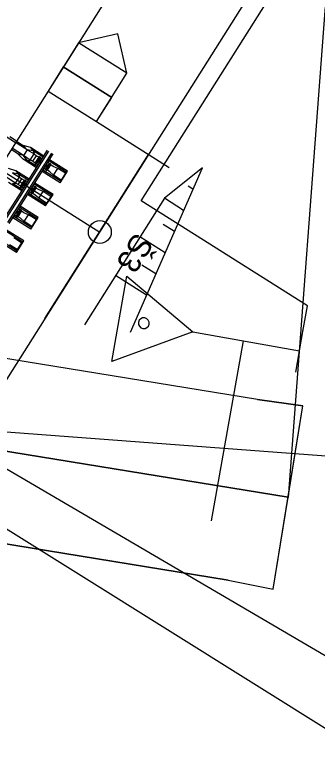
# Model space of a CAD drawing. Extents: x -743359 to -742769, y -1127804 to -1126284.
# Drawn here: x -743170.26 to -743163.64, y -1127104.78 to -1127088.87 of the extents above; entities that cross this region are included whole.
import ezdxf

# ---------------------------------------------------------------- set-up
doc = ezdxf.new("R2010")
doc.units = 0
for name, color, linetype in [('_Zabezpečovací zařízení', 7, 'Continuous'), ('_Zabezpečovací zařízení_trasa', 7, 'Continuous'), ('bublina_fialová_čára_tenká', 7, 'Continuous'), ('KOL_ROST', 7, 'Continuous'), ('KOMUNIKACE_KRAJNICE', 7, 'Continuous'), ('OSA', 7, 'Continuous'), ('OSA_KOMUNIKACE', 7, 'Continuous'), ('SMER_VYS_VYROVNANI', 7, 'Continuous'), ('SRAFA_UPRAVA', 7, 'Continuous'), ('SVAH', 7, 'Continuous'), ('TRATIVOD', 7, 'Continuous')]:
    doc.layers.add(name, color=color, linetype=linetype)

msp = doc.modelspace()

# ---------------------------------------------------------------- linework, layer by layer
at = {"layer": '_Zabezpečovací zařízení'}
for p, q in [((-743168.004, -1127089.286), (-743168.865, -1127089.483)), ((-743167.807, -1127090.147), (-743168.004, -1127089.286)), ((-743168.865, -1127089.483), (-743169.53, -1127090.542)), ((-743167.807, -1127090.147), (-743168.865, -1127089.483)), ((-743169.198, -1127090.012), (-743168.139, -1127090.677)), ((-743168.471, -1127091.206), (-743167.807, -1127090.147)), ((-743169.53, -1127090.542), (-743168.471, -1127091.206)), ((-743168.139, -1127096.449), (-743167.81, -1127094.588)), ((-743167.81, -1127094.588), (-743166.363, -1127095.804)), ((-743166.363, -1127095.804), (-743168.139, -1127096.449)), ((-743166.363, -1127095.804), (-743164.036, -1127096.216)), ((-743164.119, -1127096.681), (-743163.954, -1127095.75)), ((-743165.267, -1127095.997), (-743165.964, -1127099.936))]:
    msp.add_line(p, q, dxfattribs=at)
msp.add_lwpolyline([(-743168.471, -1127091.206), (-743168.139, -1127090.677), (-743169.198, -1127090.012), (-743169.53, -1127090.542), (-743168.471, -1127091.206)], dxfattribs=at)
for start, end in [(79.9608, 259.9608), (259.9608, 79.9608)]:
    msp.add_arc((-743167.437, -1127095.614), 0.118, start, end, dxfattribs=at)
at = {"layer": '_Zabezpečovací zařízení_trasa'}
for points in [[(-743164.036, -1127096.193), (-743163.862, -1127095.231), (-743167.492, -1127092.937), (-743158.53, -1127078.745)], [(-743168.471, -1127091.206), (-743166.88, -1127092.211)]]:
    msp.add_lwpolyline(points, dxfattribs=at)
at = {"layer": 'bublina_fialová_čára_tenká'}
for p, q in [((-743160.679, -1127051.634), (-743164.286, -1127099.423)), ((-743129.509, -1127122.8), (-743175.485, -1127095.847)), ((-743148.502, -1127099.644), (-743174.29, -1127097.707)), ((-743109.419, -1127138.306), (-743174.121, -1127097.814))]:
    msp.add_line(p, q, dxfattribs=at)
at = {"layer": 'KOL_ROST'}
for p, q in [((-743170.487, -1127091.505), (-743170.238, -1127091.662)), ((-743170.219, -1127091.633), (-743170.367, -1127091.539)), ((-743169.988, -1127091.82), (-743170.238, -1127091.662)), ((-743170.219, -1127091.633), (-743170.071, -1127091.726)), ((-743170.188, -1127091.912), (-743170.336, -1127091.819)), ((-743169.916, -1127091.776), (-743170.071, -1127091.726)), ((-743169.988, -1127091.82), (-743170.071, -1127091.726)), ((-743169.988, -1127091.82), (-743170.068, -1127091.947)), ((-743169.988, -1127091.82), (-743169.833, -1127091.912)), ((-743169.857, -1127091.847), (-743169.988, -1127091.82)), ((-743169.916, -1127091.776), (-743169.857, -1127091.847)), ((-743169.624, -1127091.961), (-743169.916, -1127091.776)), ((-743169.864, -1127092.342), (-743169.544, -1127091.834)), ((-743170.077, -1127092.03), (-743170.188, -1127091.912)), ((-743170.068, -1127091.947), (-743170.188, -1127091.912)), ((-743169.988, -1127092.054), (-743170.068, -1127091.947)), ((-743169.918, -1127092.047), (-743169.833, -1127091.912)), ((-743169.861, -1127092.072), (-743169.786, -1127091.953)), ((-743169.857, -1127091.847), (-743169.833, -1127091.912)), ((-743169.639, -1127091.986), (-743169.857, -1127091.847)), ((-743169.833, -1127091.912), (-743169.786, -1127091.953)), ((-743169.831, -1127092.362), (-743169.511, -1127091.855)), ((-743169.786, -1127091.953), (-743169.734, -1127091.98)), ((-743169.77, -1127092.401), (-743169.45, -1127091.894)), ((-743169.737, -1127092.422), (-743169.417, -1127091.914)), ((-743169.734, -1127091.98), (-743169.719, -1127091.976)), ((-743169.661, -1127092.02), (-743169.696, -1127091.997)), ((-743170.077, -1127092.03), (-743169.988, -1127092.054)), ((-743169.784, -1127092.215), (-743170.077, -1127092.03)), ((-743169.988, -1127092.054), (-743169.918, -1127092.047)), ((-743169.768, -1127092.19), (-743169.988, -1127092.054)), ((-743169.861, -1127092.072), (-743169.814, -1127092.107)), ((-743169.814, -1127092.107), (-743169.811, -1127092.123)), ((-743169.747, -1127092.156), (-743169.783, -1127092.134)), ((-743169.754, -1127092.089), (-743169.755, -1127092.081)), ((-743169.716, -1127092.106), (-743169.755, -1127092.081)), ((-743169.716, -1127092.106), (-743169.754, -1127092.089)), ((-743169.725, -1127092.043), (-743169.731, -1127092.043)), ((-743169.731, -1127092.043), (-743169.692, -1127092.068)), ((-743169.692, -1127092.068), (-743169.725, -1127092.043)), ((-743169.692, -1127092.068), (-743169.716, -1127092.106)), ((-743169.565, -1127092.149), (-743169.589, -1127092.186)), ((-743169.525, -1127092.173), (-743169.565, -1127092.149)), ((-743169.565, -1127092.149), (-743169.527, -1127092.167)), ((-743169.5, -1127092.124), (-743169.535, -1127092.101)), ((-743169.12, -1127092.318), (-743169.513, -1127092.067)), ((-743169.102, -1127092.29), (-743169.497, -1127092.041)), ((-743169.47, -1127092.152), (-743169.472, -1127092.135)), ((-743169.47, -1127092.152), (-743169.472, -1127092.135)), ((-743169.419, -1127092.185), (-743169.47, -1127092.153)), ((-743169.419, -1127092.185), (-743169.47, -1127092.153)), ((-743170.237, -1127092.284), (-743170.391, -1127092.234)), ((-743170.237, -1127092.284), (-743170.177, -1127092.354)), ((-743169.944, -1127092.468), (-743170.237, -1127092.284)), ((-743169.262, -1127092.544), (-743169.657, -1127092.295)), ((-743169.245, -1127092.516), (-743169.641, -1127092.269)), ((-743169.584, -1127092.257), (-743169.619, -1127092.235)), ((-743169.589, -1127092.186), (-743169.549, -1127092.211)), ((-743169.589, -1127092.186), (-743169.556, -1127092.213)), ((-743169.545, -1127092.271), (-743169.562, -1127092.277)), ((-743169.556, -1127092.213), (-743169.549, -1127092.211)), ((-743169.494, -1127092.304), (-743169.545, -1127092.271)), ((-743169.527, -1127092.167), (-743169.525, -1127092.173)), ((-743169.412, -1127092.376), (-743169.494, -1127092.304)), ((-743169.318, -1127092.228), (-743169.419, -1127092.185)), ((-743169.318, -1127092.228), (-743169.419, -1127092.185)), ((-743169.412, -1127092.376), (-743169.318, -1127092.228)), ((-743169.149, -1127092.335), (-743169.318, -1127092.228)), ((-743169.262, -1127092.544), (-743169.102, -1127092.29)), ((-743169.117, -1127092.314), (-743169.149, -1127092.335)), ((-743170.308, -1127092.327), (-743170.153, -1127092.419)), ((-743170.177, -1127092.354), (-743170.308, -1127092.327)), ((-743170.239, -1127092.555), (-743170.153, -1127092.419)), ((-743170.184, -1127092.849), (-743169.864, -1127092.342)), ((-743170.181, -1127092.579), (-743170.106, -1127092.461)), ((-743170.177, -1127092.354), (-743170.153, -1127092.419)), ((-743169.96, -1127092.493), (-743170.177, -1127092.354)), ((-743170.153, -1127092.419), (-743170.106, -1127092.461)), ((-743170.151, -1127092.87), (-743169.831, -1127092.362)), ((-743170.106, -1127092.461), (-743170.055, -1127092.488)), ((-743170.09, -1127092.908), (-743169.77, -1127092.401)), ((-743170.057, -1127092.929), (-743169.737, -1127092.422)), ((-743169.242, -1127092.483), (-743169.412, -1127092.376)), ((-743169.149, -1127092.335), (-743169.242, -1127092.483)), ((-743170.104, -1127092.722), (-743170.397, -1127092.537)), ((-743170.308, -1127092.561), (-743170.239, -1127092.555)), ((-743170.089, -1127092.697), (-743170.308, -1127092.561)), ((-743170.181, -1127092.579), (-743170.134, -1127092.614)), ((-743170.134, -1127092.614), (-743170.131, -1127092.63)), ((-743170.074, -1127092.596), (-743170.075, -1127092.589)), ((-743170.036, -1127092.614), (-743170.075, -1127092.589)), ((-743170.036, -1127092.614), (-743170.074, -1127092.596)), ((-743170.055, -1127092.488), (-743170.039, -1127092.484)), ((-743170.045, -1127092.55), (-743170.051, -1127092.551)), ((-743170.051, -1127092.551), (-743170.012, -1127092.576)), ((-743170.012, -1127092.576), (-743170.045, -1127092.55)), ((-743170.012, -1127092.576), (-743170.036, -1127092.614)), ((-743169.981, -1127092.527), (-743170.016, -1127092.504)), ((-743169.82, -1127092.631), (-743169.855, -1127092.608)), ((-743169.44, -1127092.825), (-743169.833, -1127092.574)), ((-743169.422, -1127092.798), (-743169.817, -1127092.549)), ((-743169.247, -1127092.52), (-743169.242, -1127092.483)), ((-743170.067, -1127092.664), (-743170.103, -1127092.642)), ((-743169.565, -1127093.023), (-743169.961, -1127092.777)), ((-743169.904, -1127092.764), (-743169.94, -1127092.742)), ((-743169.885, -1127092.656), (-743169.909, -1127092.694)), ((-743169.909, -1127092.694), (-743169.869, -1127092.719)), ((-743169.909, -1127092.694), (-743169.876, -1127092.721)), ((-743169.845, -1127092.681), (-743169.885, -1127092.656)), ((-743169.885, -1127092.656), (-743169.847, -1127092.675)), ((-743169.865, -1127092.779), (-743169.882, -1127092.784)), ((-743169.876, -1127092.721), (-743169.869, -1127092.719)), ((-743169.814, -1127092.811), (-743169.865, -1127092.779)), ((-743169.847, -1127092.675), (-743169.845, -1127092.681)), ((-743169.79, -1127092.66), (-743169.792, -1127092.642)), ((-743169.79, -1127092.66), (-743169.792, -1127092.642)), ((-743169.739, -1127092.692), (-743169.79, -1127092.66)), ((-743169.739, -1127092.692), (-743169.79, -1127092.66)), ((-743169.638, -1127092.735), (-743169.739, -1127092.692)), ((-743169.638, -1127092.735), (-743169.739, -1127092.692)), ((-743169.732, -1127092.883), (-743169.638, -1127092.735)), ((-743169.469, -1127092.842), (-743169.638, -1127092.735)), ((-743169.583, -1127093.051), (-743169.422, -1127092.798)), ((-743170.505, -1127093.356), (-743170.184, -1127092.849)), ((-743170.472, -1127093.377), (-743170.151, -1127092.87)), ((-743170.411, -1127093.415), (-743170.09, -1127092.908)), ((-743170.378, -1127093.436), (-743170.057, -1127092.929)), ((-743169.583, -1127093.051), (-743169.977, -1127092.802)), ((-743169.732, -1127092.883), (-743169.814, -1127092.811)), ((-743169.563, -1127092.99), (-743169.732, -1127092.883)), ((-743169.469, -1127092.842), (-743169.563, -1127092.99)), ((-743169.437, -1127092.821), (-743169.469, -1127092.842)), ((-743170.14, -1127093.138), (-743170.175, -1127093.116)), ((-743169.761, -1127093.333), (-743170.153, -1127093.081)), ((-743169.743, -1127093.305), (-743170.137, -1127093.056)), ((-743169.568, -1127093.028), (-743169.563, -1127092.99)), ((-743170.224, -1127093.272), (-743170.26, -1127093.25)), ((-743170.205, -1127093.163), (-743170.229, -1127093.201)), ((-743170.229, -1127093.201), (-743170.19, -1127093.226)), ((-743170.229, -1127093.201), (-743170.197, -1127093.228)), ((-743170.166, -1127093.188), (-743170.205, -1127093.163)), ((-743170.205, -1127093.163), (-743170.168, -1127093.182)), ((-743170.197, -1127093.228), (-743170.19, -1127093.226)), ((-743170.168, -1127093.182), (-743170.166, -1127093.188)), ((-743170.11, -1127093.167), (-743170.113, -1127093.15)), ((-743170.11, -1127093.167), (-743170.113, -1127093.15)), ((-743170.059, -1127093.2), (-743170.111, -1127093.167)), ((-743170.059, -1127093.2), (-743170.111, -1127093.167)), ((-743169.959, -1127093.243), (-743170.059, -1127093.2)), ((-743169.959, -1127093.243), (-743170.059, -1127093.2)), ((-743170.052, -1127093.391), (-743169.959, -1127093.243)), ((-743169.79, -1127093.349), (-743169.959, -1127093.243)), ((-743169.903, -1127093.559), (-743170.298, -1127093.31)), ((-743169.885, -1127093.531), (-743170.281, -1127093.284)), ((-743170.186, -1127093.286), (-743170.202, -1127093.292)), ((-743170.134, -1127093.318), (-743170.186, -1127093.286)), ((-743170.052, -1127093.391), (-743170.134, -1127093.318)), ((-743169.883, -1127093.497), (-743170.052, -1127093.391)), ((-743169.903, -1127093.559), (-743169.743, -1127093.305)), ((-743169.79, -1127093.349), (-743169.883, -1127093.497)), ((-743169.758, -1127093.329), (-743169.79, -1127093.349)), ((-743170.081, -1127093.84), (-743170.474, -1127093.589)), ((-743170.063, -1127093.812), (-743170.458, -1127093.563)), ((-743169.888, -1127093.535), (-743169.883, -1127093.497)), ((-743170.11, -1127093.857), (-743170.279, -1127093.75)), ((-743170.223, -1127094.066), (-743170.618, -1127093.817)), ((-743170.206, -1127094.038), (-743170.602, -1127093.791)), ((-743170.203, -1127094.005), (-743170.372, -1127093.898)), ((-743170.223, -1127094.066), (-743170.063, -1127093.812)), ((-743170.11, -1127093.857), (-743170.203, -1127094.005)), ((-743170.078, -1127093.836), (-743170.11, -1127093.857)), ((-743170.208, -1127094.042), (-743170.203, -1127094.005))]:
    msp.add_line(p, q, dxfattribs=at)
for points in [[(-743169.861, -1127092.072), (-743169.918, -1127092.047), (-743170.068, -1127091.947), (-743170.318, -1127091.789)], [(-743169.734, -1127091.98), (-743169.814, -1127092.107)], [(-743169.788, -1127092.133), (-743169.699, -1127091.993)], [(-743169.696, -1127091.997), (-743169.725, -1127092.043)], [(-743169.696, -1127091.997), (-743169.699, -1127091.993)], [(-743169.783, -1127092.134), (-743169.788, -1127092.133)], [(-743169.754, -1127092.089), (-743169.783, -1127092.134)], [(-743169.495, -1127092.125), (-743169.58, -1127092.261)], [(-743169.545, -1127092.271), (-743169.47, -1127092.152)], [(-743169.527, -1127092.167), (-743169.5, -1127092.124)], [(-743169.5, -1127092.124), (-743169.495, -1127092.125)], [(-743169.5, -1127092.124), (-743169.495, -1127092.125)], [(-743170.181, -1127092.579), (-743170.239, -1127092.555), (-743170.388, -1127092.454), (-743170.638, -1127092.297)], [(-743169.584, -1127092.257), (-743169.556, -1127092.213)], [(-743169.584, -1127092.257), (-743169.58, -1127092.261)], [(-743170.055, -1127092.488), (-743170.134, -1127092.614)], [(-743170.108, -1127092.64), (-743170.019, -1127092.5)], [(-743170.103, -1127092.642), (-743170.108, -1127092.64)], [(-743170.074, -1127092.596), (-743170.103, -1127092.642)], [(-743170.016, -1127092.504), (-743170.045, -1127092.55)], [(-743170.016, -1127092.504), (-743170.019, -1127092.5)], [(-743169.815, -1127092.632), (-743169.901, -1127092.768)], [(-743169.847, -1127092.675), (-743169.82, -1127092.631)], [(-743169.82, -1127092.631), (-743169.815, -1127092.632)], [(-743169.82, -1127092.631), (-743169.815, -1127092.632)], [(-743169.904, -1127092.764), (-743169.877, -1127092.721)], [(-743169.904, -1127092.764), (-743169.901, -1127092.768)], [(-743169.865, -1127092.779), (-743169.79, -1127092.66)], [(-743170.224, -1127093.272), (-743170.197, -1127093.228)], [(-743170.224, -1127093.272), (-743170.221, -1127093.275)], [(-743170.135, -1127093.14), (-743170.221, -1127093.275)], [(-743170.186, -1127093.286), (-743170.11, -1127093.167)], [(-743170.168, -1127093.182), (-743170.14, -1127093.138)], [(-743170.14, -1127093.138), (-743170.135, -1127093.14)], [(-743170.14, -1127093.138), (-743170.135, -1127093.14)]]:
    msp.add_lwpolyline(points, dxfattribs=at)
for centre, radius in [((-743169.726, -1127092.074), 0.0195), ((-743169.726, -1127092.074), 0.0155), ((-743169.726, -1127092.074), 0.0115), ((-743169.555, -1127092.182), 0.0195), ((-743169.555, -1127092.182), 0.0155), ((-743169.555, -1127092.182), 0.0115), ((-743170.046, -1127092.581), 0.0195), ((-743170.046, -1127092.581), 0.0155), ((-743170.046, -1127092.581), 0.0115), ((-743169.875, -1127092.689), 0.0195), ((-743169.875, -1127092.689), 0.0155), ((-743169.875, -1127092.689), 0.0115), ((-743170.195, -1127093.196), 0.0195), ((-743170.195, -1127093.196), 0.0155), ((-743170.195, -1127093.196), 0.0115)]:
    msp.add_circle(centre, radius, dxfattribs=at)
for centre, radius, start, end in [((-743169.713, -1127091.99), 0.0143, 346.7248, 112.2532), ((-743169.797, -1127092.122), 0.0143, 183.2195, 308.7478), ((-743169.486, -1127092.136), 0.0137, 2.1748, 130.3968), ((-743169.486, -1127092.136), 0.0137, 2.1748, 130.3968), ((-743169.567, -1127092.264), 0.0137, 165.0758, 293.2978), ((-743170.117, -1127092.629), 0.0143, 183.2195, 308.7478), ((-743170.033, -1127092.497), 0.0143, 346.7248, 112.2532), ((-743169.806, -1127092.643), 0.0137, 2.1748, 130.3968), ((-743169.806, -1127092.643), 0.0137, 2.1748, 130.3968), ((-743169.887, -1127092.772), 0.0137, 165.0758, 293.2978), ((-743170.208, -1127093.279), 0.0137, 165.0758, 293.2978), ((-743170.126, -1127093.15), 0.0137, 2.1748, 130.3968), ((-743170.126, -1127093.15), 0.0137, 2.1748, 130.3968)]:
    msp.add_arc(centre, radius, start, end, dxfattribs=at)
at = {"layer": 'KOMUNIKACE_KRAJNICE'}
for p, q in [((-743164.95, -1127097.281), (-743171.211, -1127096.261)), ((-743164.95, -1127097.281), (-743163.96, -1127097.421)), ((-743164.612, -1127101.425), (-743163.96, -1127097.421)), ((-743165.593, -1127101.229), (-743173.53, -1127099.936)), ((-743165.593, -1127101.229), (-743164.612, -1127101.425))]:
    msp.add_line(p, q, dxfattribs=at)
at = {"layer": 'OSA'}
msp.add_lwpolyline([(-743169.53, -1127090.542), (-743178.712, -1127105.086)], dxfattribs=at)
at = {"layer": 'OSA_KOMUNIKACE'}
msp.add_line((-743164.284, -1127099.415), (-743182.5, -1127096.45), dxfattribs=at)
at = {"layer": 'SMER_VYS_VYROVNANI'}
msp.add_lwpolyline([(-743143.427, -1127049.192), (-743169.53, -1127090.542)], dxfattribs=at)
at = {"layer": 'SRAFA_UPRAVA'}
for p, q in [((-743164.95, -1127097.281), (-743171.211, -1127096.261)), ((-743163.96, -1127097.421), (-743164.95, -1127097.281)), ((-743164.284, -1127099.415), (-743163.96, -1127097.421)), ((-743172.37, -1127098.099), (-743164.284, -1127099.415)), ((-743164.284, -1127099.415), (-743172.37, -1127098.099)), ((-743164.612, -1127101.425), (-743164.284, -1127099.415)), ((-743173.53, -1127099.936), (-743165.593, -1127101.229)), ((-743165.593, -1127101.229), (-743164.612, -1127101.425))]:
    msp.add_line(p, q, dxfattribs=at)
at = {"layer": 'SVAH'}
for p, q in [((-743166.364, -1127092.684), (-743166.469, -1127092.618)), ((-743166.567, -1127093.147), (-743166.987, -1127092.882)), ((-743166.77, -1127093.61), (-743167.012, -1127093.458)), ((-743166.973, -1127094.073), (-743167.521, -1127093.728)), ((-743167.176, -1127094.536), (-743167.482, -1127094.344)), ((-743167.379, -1127095), (-743168.055, -1127094.573))]:
    msp.add_line(p, q, dxfattribs=at)
for points in [[(-743167.343, -1127091.922), (-743169.607, -1127095.509)], [(-743166.158, -1127092.217), (-743166.987, -1127092.882), (-743168.735, -1127095.651)], [(-743166.161, -1127092.221), (-743167.737, -1127095.814)]]:
    msp.add_lwpolyline(points, dxfattribs=at)
at = {"layer": 'TRATIVOD'}
for points in [[(-743175.637, -1127105.086), (-743168.399, -1127093.621), (-743157.384, -1127076.172), (-743151.775, -1127072.311)], [(-743172.796, -1127090.845), (-743168.399, -1127093.621)]]:
    msp.add_lwpolyline(points, dxfattribs=at)
msp.add_circle((-743168.399, -1127093.621), 0.25, dxfattribs=at)

# ---------------------------------------------------------------- texts
msp.add_text('Š3', height=0.5, rotation=238, dxfattribs=at).set_placement((-743167.625, -1127093.603))

doc.saveas('drawing.dxf')
